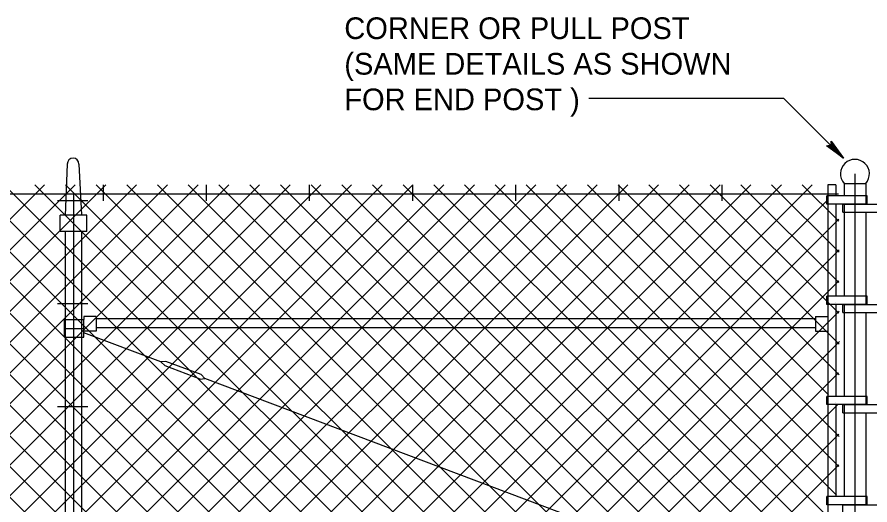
# Model space of a CAD drawing. Extents: x 13 to 918, y -903 to 879.
# Drawn here: x 455.7 to 578.5, y 37 to 107.3 of the extents above; entities that cross this region are included whole.
import ezdxf

# ---------------------------------------------------------------- set-up
doc = ezdxf.new("R2010")
doc.units = 0
doc.layers.add('2', color=7, linetype='Continuous')
doc.layers.add('3', color=7, linetype='Continuous')

msp = doc.modelspace()

# ---------------------------------------------------------------- linework, layer by layer
at = {"layer": '2'}
for p, q in [((538.0515, 95.66575), (566.05775, 95.66575)), ((574.70575, 87.01775), (566.05775, 95.66575)), ((462.97875, 86.1635), (462.67875, 78.75925)), ((464.658, 86.1635), (465.02875, 78.8365)), ((576.35375, 84.74475), (576.35375, 1.33025)), ((468.17675, 80.878), (468.17675, 83.18225)), ((483.0205, 80.878), (483.0205, 83.18225)), ((497.86625, 80.878), (497.86625, 83.18225)), ((512.712, 80.878), (512.712, 83.18225)), ((527.55575, 80.878), (527.55575, 83.18225)), ((542.40175, 80.878), (542.40175, 83.18225)), ((557.2455, 80.878), (557.2455, 83.18225)), ((572.44125, 83.18225), (572.44125, 17.81775)), ((573.61625, 83.18225), (572.44125, 83.18225)), ((573.61625, 83.18225), (573.61625, 81.526)), ((574.79125, 83.36775), (577.91625, 83.36775)), ((574.79125, 83.36775), (574.79125, 81.54675)), ((577.91625, 83.36775), (577.91625, 80.38225)), ((129.09125, 81.88225), (573.9705, 81.88225)), ((463.85375, 81.88225), (463.85375, -20.274)), ((578.09325, 81.5615), (572.33075, 81.5615)), ((572.33075, 80.3865), (572.33075, 81.5615)), ((578.09325, 80.3865), (578.09325, 81.5615)), ((465.937, 80.85925), (461.5475, 80.85925)), ((463.85375, 80.85925), (463.85375, 21.351)), ((578.09325, 80.3865), (572.33075, 80.3865)), ((573.61625, 80.38225), (573.61625, 67.099)), ((574.61425, 80.3865), (580.37675, 80.3865)), ((574.61425, 79.2115), (574.61425, 80.3865)), ((574.79125, 80.34275), (574.79125, 67.1365)), ((576.35375, 80.974), (576.35375, 80.974)), ((576.35375, 79.799), (576.35375, 79.799)), ((576.35375, 79.799), (576.35375, 79.799)), ((465.812, 78.80725), (461.958, 78.80725)), ((461.958, 76.4615), (461.958, 78.80725)), ((465.812, 76.4615), (465.812, 78.80725)), ((574.61425, 79.2115), (580.37675, 79.2115)), ((577.91625, 79.15925), (577.91625, 65.89675)), ((465.812, 76.4615), (461.958, 76.4615)), ((462.67875, 76.4615), (462.67875, 7.05525)), ((465.02875, 76.4615), (465.02875, 7.6865)), ((578.09325, 67.124), (572.33075, 67.124)), ((572.33075, 65.949), (572.33075, 67.124)), ((576.35375, 66.5365), (576.35375, 66.5365)), ((576.35375, 66.5365), (576.35375, 66.5365)), ((576.35375, 66.5365), (576.35375, 66.5365)), ((576.35375, 66.5365), (576.35375, 66.5365)), ((578.09325, 65.949), (578.09325, 67.124)), ((465.937, 66.0135), (461.5475, 66.0135)), ((578.09325, 65.949), (572.33075, 65.949)), ((573.61625, 66.24275), (573.61625, 66.24275)), ((573.61625, 65.93425), (573.61625, 52.70725)), ((574.61425, 65.949), (580.37675, 65.949)), ((574.61425, 64.774), (574.61425, 65.949)), ((574.79125, 65.93425), (574.79125, 52.66975)), ((576.35375, 65.3615), (576.35375, 65.3615)), ((576.35375, 65.3615), (576.35375, 65.3615)), ((576.35375, 65.3615), (576.35375, 65.3615)), ((576.35375, 65.3615), (576.35375, 65.3615)), ((576.35375, 65.3615), (576.35375, 65.3615)), ((467.1455, 64.174), (465.36, 64.174)), ((465.36, 64.174), (465.36, 63.78225)), ((467.1455, 64.174), (467.1455, 62.0905)), ((467.24125, 63.89675), (570.75175, 63.89675)), ((570.65575, 64.174), (572.44125, 64.174)), ((570.65575, 64.174), (570.65575, 62.0905)), ((574.61425, 64.774), (580.37675, 64.774)), ((577.91625, 64.76975), (577.91625, 51.4865)), ((462.56825, 63.78225), (465.36, 63.78225)), ((462.56825, 61.22175), (462.56825, 63.78225)), ((463.85375, 63.13225), (463.85375, 63.13225)), ((463.85375, 63.13225), (463.85375, 63.13225)), ((463.85375, 63.13225), (463.85375, 63.13225)), ((463.85375, 63.13225), (463.85375, 63.13225)), ((465.36, 62.48225), (465.36, 63.78225)), ((465.36, 63.13225), (465.36, 63.13225)), ((465.36, 63.13225), (465.36, 63.13225)), ((465.36, 63.13225), (465.36, 63.13225)), ((465.36, 63.13225), (465.36, 63.13225)), ((467.1455, 62.6115), (570.65575, 62.6115)), ((572.44125, 63.13225), (572.44125, 63.13225)), ((462.56825, 62.48225), (465.36, 62.48225)), ((465.36, 61.22175), (465.36, 62.48225)), ((467.1455, 62.0905), (465.36, 62.0905)), ((476.42675, 57.674), (465.36, 61.853)), ((570.65575, 62.0905), (572.44125, 62.0905)), ((462.56825, 61.22175), (465.36, 61.22175)), ((477.18075, 57.7365), (476.42675, 57.674)), ((482.22875, 55.83225), (477.18075, 57.7365)), ((476.42675, 57.674), (477.0455, 57.09275)), ((482.10575, 55.18225), (477.0455, 57.09275)), ((482.10575, 55.18225), (482.76425, 55.28225)), ((482.76425, 55.28225), (482.22875, 55.83225)), ((574.63075, 20.59675), (482.76425, 55.28225)), ((578.09325, 52.6885), (572.33075, 52.6885)), ((572.33075, 51.5135), (572.33075, 52.6885)), ((573.61625, 51.80725), (573.61625, 51.80725)), ((576.35375, 52.101), (576.35375, 52.101)), ((576.35375, 52.101), (576.35375, 52.101)), ((576.35375, 52.101), (576.35375, 52.101)), ((578.09325, 51.5135), (578.09325, 52.6885)), ((465.937, 51.16975), (461.5475, 51.16975)), ((578.09325, 51.5135), (572.33075, 51.5135)), ((573.61625, 51.4865), (573.61625, 38.28025)), ((574.61425, 51.5135), (580.37675, 51.5135)), ((574.61425, 50.3385), (574.61425, 51.5135)), ((574.61425, 50.3385), (580.37675, 50.3385)), ((574.79125, 51.524), (574.79125, 38.2405)), ((576.35375, 50.926), (576.35375, 50.926)), ((576.35375, 50.926), (576.35375, 50.926)), ((576.35375, 50.926), (576.35375, 50.926)), ((576.35375, 50.926), (576.35375, 50.926)), ((577.91625, 50.32175), (577.91625, 37.05725)), ((578.09325, 38.251), (572.33075, 38.251)), ((572.33075, 37.076), (572.33075, 38.251)), ((578.09325, 37.076), (578.09325, 38.251)), ((578.09325, 37.076), (572.33075, 37.076)), ((574.61425, 37.076), (580.37675, 37.076)), ((574.61425, 35.901), (574.61425, 37.076)), ((576.35375, 37.6635), (576.35375, 37.6635)), ((576.35375, 37.6635), (576.35375, 37.6635))]:
    msp.add_line(p, q, dxfattribs=at)
for points in [[(394.33925, 17.81775), (459.70375, 83.18225)], [(398.758, 17.81775), (464.1225, 83.18225)], [(403.17875, 17.81775), (468.54325, 83.18225)], [(407.5975, 17.81775), (472.962, 83.18225)], [(475.0475, 17.81775), (409.683, 83.18225)], [(412.01625, 17.81775), (477.38075, 83.18225)], [(479.46625, 17.81775), (414.10175, 83.18225)], [(416.437, 17.81775), (481.80175, 83.18225)], [(483.885, 17.81775), (418.5205, 83.18225)], [(420.85575, 17.81775), (486.2205, 83.18225)], [(488.30575, 17.81775), (422.94125, 83.18225)], [(425.2745, 17.81775), (490.63925, 83.18225)], [(492.7245, 17.81775), (427.36, 83.18225)], [(429.6955, 17.81775), (495.06, 83.18225)], [(497.14325, 17.81775), (431.77875, 83.18225)], [(434.11425, 17.81775), (499.47875, 83.18225)], [(501.56425, 17.81775), (436.1995, 83.18225)], [(438.533, 17.81775), (503.8975, 83.18225)], [(505.983, 17.81775), (440.61825, 83.18225)], [(442.95375, 17.81775), (508.31825, 83.18225)], [(510.40175, 17.81775), (445.037, 83.18225)], [(447.3725, 17.81775), (512.737, 83.18225)], [(514.8225, 17.81775), (449.458, 83.18225)], [(451.79125, 17.81775), (517.15575, 83.18225)], [(519.24125, 17.81775), (453.87675, 83.18225)], [(456.212, 17.81775), (521.57675, 83.18225)], [(523.66, 17.81775), (458.2955, 83.18225)], [(460.63075, 17.81775), (525.9955, 83.18225)], [(528.08075, 17.81775), (462.71625, 83.18225)], [(465.0495, 17.81775), (530.41425, 83.18225)], [(532.4995, 17.81775), (467.135, 83.18225)], [(469.4705, 17.81775), (534.835, 83.18225)], [(536.91825, 17.81775), (471.55375, 83.18225)], [(473.88925, 17.81775), (539.25375, 83.18225)], [(541.337, 17.81775), (475.9745, 83.18225)], [(478.308, 17.81775), (543.6725, 83.18225)], [(545.758, 17.8155), (480.39325, 83.18225)], [(482.72675, 17.81775), (548.09125, 83.18225)], [(550.17675, 17.81775), (484.812, 83.18225)], [(487.1475, 17.81775), (552.512, 83.18225)], [(554.5955, 17.81775), (489.233, 83.18225)], [(491.56625, 17.81775), (556.93075, 83.18225)], [(559.01625, 17.8155), (493.65175, 83.18225)], [(495.985, 17.81775), (561.3495, 83.18225)], [(563.435, 17.81775), (498.0705, 83.18225)], [(500.40575, 17.81775), (565.7705, 83.18225)], [(567.85575, 17.8155), (502.49125, 83.18225)], [(504.8245, 17.81775), (570.18925, 83.18225)], [(572.2745, 17.81775), (506.91, 83.18225)], [(574.0995, 20.4115), (511.32875, 83.18225)], [(574.1245, 24.80725), (515.7495, 83.18225)], [(574.05375, 29.299), (520.16825, 83.18225)], [(574.03075, 33.7405), (524.587, 83.18225)], [(573.7205, 38.46975), (529.00575, 83.18225)], [(574.03075, 42.578), (533.42675, 83.18225)], [(574.10375, 46.926), (537.8455, 83.18225)], [(572.55375, 52.89475), (542.26425, 83.18225)], [(574.0955, 55.77175), (546.685, 83.18225)], [(574.09125, 60.19675), (551.10375, 83.18225)], [(574.03925, 64.66775), (555.5225, 83.18225)], [(574.0455, 69.08225), (559.94325, 83.18225)], [(574.0975, 73.449), (564.362, 83.18225)], [(574.0455, 77.91975), (568.78075, 83.18225)], [(509.24325, 17.81775), (572.47875, 81.053)], [(513.66425, 17.81775), (574.058, 78.2115)], [(518.08075, 17.8155), (574.06425, 73.799)], [(522.50175, 17.81775), (574.04125, 69.35525)], [(526.9225, 17.81775), (574.0745, 64.96975)], [(531.34125, 17.81775), (574.108, 60.58425)], [(535.76, 17.81775), (574.008, 56.0655)], [(540.17875, 17.8155), (573.85375, 51.4905)], [(544.5995, 17.81775), (574.0495, 47.26775)], [(549.01825, 17.81775), (574.0245, 42.824)]]:
    msp.add_lwpolyline(points, dxfattribs=at)
for centre, radius, start, end in [((463.81839, 86.16354), 0.83958, 0, 180), ((576.35381, 84.74479), 2.0825, 318.6091972, 221.3358167)]:
    msp.add_arc(centre, radius, start, end, dxfattribs=at)
at = {"layer": '3'}
msp.add_lwpolyline([(572.95175, 89.276), (572.88075, 89.05725), (574.70575, 87.01775), (572.95175, 89.276), (572.937, 89.46775), (574.70575, 87.01775), (572.68075, 88.853), (572.46625, 88.78025), (574.70575, 87.01775), (572.26, 88.79275), (572.46625, 88.78025)], dxfattribs=at)

# ---------------------------------------------------------------- texts
for s, p in [('CORNER OR PULL POST', (502.853, 104.1635)), ('(SAME DETAILS AS SHOWN', (502.853, 99.0385)), ('FOR END POST )', (502.853, 93.9135))]:
    msp.add_text(s, height=3.1249995, dxfattribs=at).set_placement(p)

doc.saveas('drawing.dxf')
